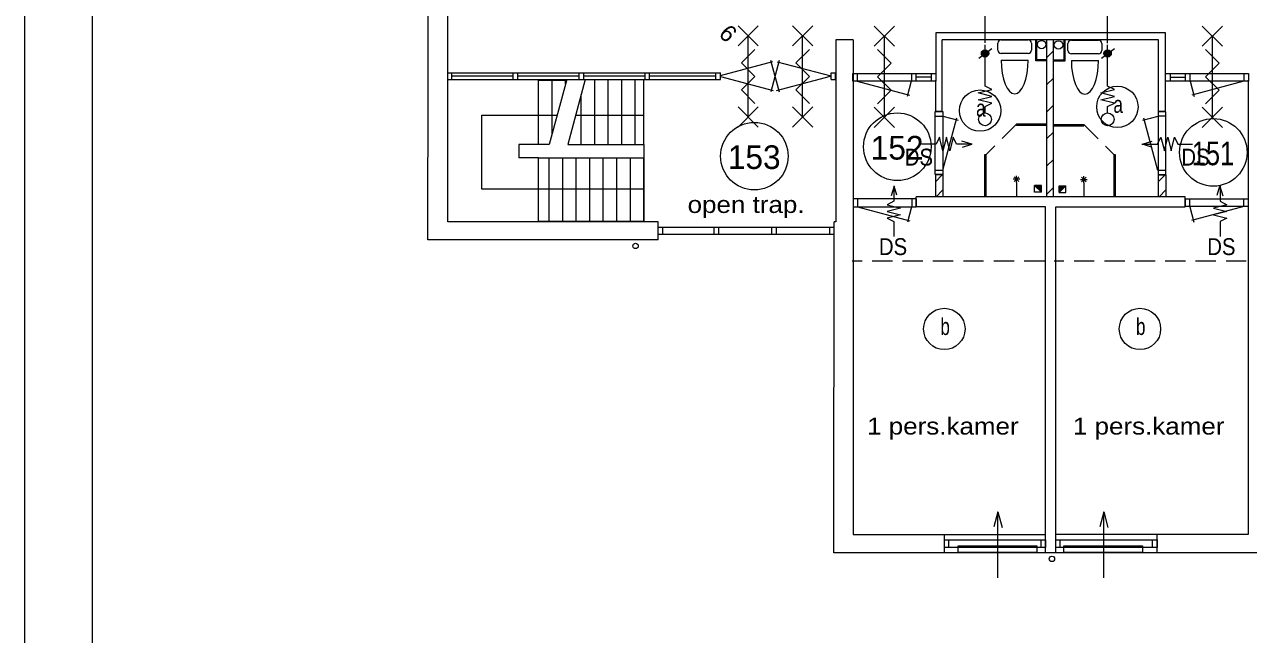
# Model space of a CAD drawing. Extents: x 295824 to 414724, y 24924 to 109024.
# Drawn here: x 295824 to 313944, y 61087 to 70117 of the extents above; entities that cross this region are included whole.
import ezdxf
from ezdxf.enums import TextEntityAlignment as Align

# ---------------------------------------------------------------- set-up
doc = ezdxf.new("R2010")
doc.units = 0
doc.header["$LTSCALE"] = 100
doc.linetypes.add('MEDIUM_DASHED', pattern=[4.5, 3, -1.5])
for name, color, linetype, lineweight in [('1', 7, 'Continuous', 13), ('16', 7, 'Continuous', 13), ('24', 7, 'Continuous', 13), ('61', 7, 'Continuous', 13)]:
    doc.layers.add(name, color=color, linetype=linetype, lineweight=lineweight)

msp = doc.modelspace()

# ---------------------------------------------------------------- hatches: boundary and pattern name
at = {"layer": '24'}
for points in [[(310097.8, 69688.9, 1), (309989.2, 69688.9, 1)], [(311913.3, 69688.9, 1), (311804.7, 69688.9, 1)]]:
    msp.add_hatch(color=256, dxfattribs=at).paths.add_polyline_path(points)
at = {"layer": '61'}
for points in [[(310777.4, 67734.4), (310877.4, 67634.4), (310877.4, 67734.4)], [(311239.8, 67729), (311139.8, 67629), (311139.8, 67729)]]:
    msp.add_hatch(color=256, dxfattribs=at).paths.add_polyline_path(points)

# ---------------------------------------------------------------- linework, layer by layer
at = {"layer": '1'}
for p, q in [((295823.6, 109023.8), (295823.6, 24923.8)), ((310043.5, 69843.4), (310043.5, 70726.3)), ((311859, 69838.4), (311859, 70726.3))]:
    msp.add_line(p, q, dxfattribs=at)
msp.add_lwpolyline([(304995.6, 108023.8), (296823.6, 108023.8), (296823.6, 25923.8), (304995.6, 25923.8)], dxfattribs=at)
at = {"layer": '16'}
for p, q in [((309470.8, 68447.5), (309420.8, 68247.5)), ((312748.2, 68447.5), (312798.2, 68247.5)), ((308594.4, 67349.3), (308794.4, 67299.3)), ((313624.7, 67349.3), (313424.7, 67299.3))]:
    msp.add_line(p, q, dxfattribs=at)
at = {"layer": '24'}
for p, q in [((310043.5, 69253.4), (310043.5, 69814.2)), ((311859, 69253.4), (311859, 69815.7)), ((309951.9, 69618), (310143.5, 69759.7)), ((311767.4, 69618), (311959, 69759.7)), ((309846.2, 68344.1), (309702, 68389.2)), ((309710.4, 68301.7), (309846.2, 68344.1)), ((312372.8, 68344.1), (312517, 68389.2)), ((312508.6, 68301.7), (312372.8, 68344.1)), ((308697.7, 67724.8), (308652.7, 67580.6)), ((308740.2, 67588.9), (308697.7, 67724.8)), ((313478.9, 67588.9), (313521.3, 67724.8)), ((313521.3, 67724.8), (313566.3, 67580.6)), ((310235, 62903.3), (310175.4, 62680.9)), ((311800.7, 62903.3), (311741.1, 62680.9))]:
    msp.add_line(p, q, dxfattribs=at)
for points in [[(310043.5, 68803.4), (310043.5, 68903.4), (310143.5, 68953.4), (309943.5, 69003.4), (310143.5, 69053.4), (309943.5, 69103.4), (310143.5, 69153.4), (310043.5, 69203.4), (310043.5, 69253.4)], [(311859, 68803.4), (311859, 68903.4), (311959, 68953.4), (311759, 69003.4), (311959, 69053.4), (311759, 69103.4), (311959, 69153.4), (311859, 69203.4), (311859, 69253.4)], [(309420.8, 68247.5), (309370.8, 68447.5), (309320.8, 68347.5), (309102, 68347.5)], [(309852, 68347.5), (309620.8, 68347.5), (309570.8, 68447.5), (309520.8, 68247.5), (309470.8, 68447.5)], [(312367, 68347.5), (312598.2, 68347.5), (312648.2, 68447.5), (312698.2, 68247.5), (312748.2, 68447.5)], [(312798.2, 68247.5), (312848.2, 68447.5), (312898.2, 68347.5), (313117, 68347.5)], [(308694.4, 67730.6), (308694.4, 67499.3), (308594.4, 67449.3), (308794.4, 67399.3), (308594.4, 67349.3)], [(313524.7, 67730.6), (313524.7, 67499.3), (313624.7, 67449.3), (313424.7, 67399.3), (313624.7, 67349.3)], [(308794.4, 67299.3), (308594.4, 67249.3), (308694.4, 67199.3), (308694.4, 66980.6)], [(313424.7, 67299.3), (313624.7, 67249.3), (313524.7, 67199.3), (313524.7, 66980.6)], [(310235, 61928.3), (310235, 62903.3), (310296.7, 62673.1)], [(311800.7, 61928.3), (311800.7, 62903.3), (311862.4, 62673.1)]]:
    msp.add_lwpolyline(points, dxfattribs=at)
for points in [[(309643.7, 62399.1), (310809.7, 62399.1), (310809.7, 62299.1), (309643.7, 62299.1)], [(311209.4, 62399.1), (312375.4, 62399.1), (312375.4, 62299.1), (311209.4, 62299.1)]]:
    msp.add_lwpolyline(points, close=True, dxfattribs=at)
for centre, radius in [((310043.5, 69688.9), 54.3), ((311859, 69688.9), 54.3), ((310043.5, 68711.8), 95), ((311859, 68711.8), 95)]:
    msp.add_circle(centre, radius, dxfattribs=at)
at = {"layer": '61'}
for p, q in [((302090.1, 69301.2), (302090.1, 72065.2)), ((306687.3, 70099), (306387.3, 69799)), ((306387.3, 70099), (306687.3, 69799)), ((306537.3, 68749), (306537.3, 69949)), ((307493.3, 70099), (307193.3, 69799)), ((307193.3, 70099), (307493.3, 69799)), ((307343.3, 68749), (307343.3, 69949)), ((308402.5, 69794.2), (308702.5, 70094.2)), ((308702.5, 69794.2), (308402.5, 70094.2)), ((313258.3, 69794.2), (313558.3, 70094.2)), ((313558.3, 69794.2), (313258.3, 70094.2)), ((308090.1, 69891.5), (308090.1, 62566.5)), ((308552.5, 69944.2), (308552.5, 68744.2)), ((309409.2, 68829.5), (309409.2, 69891.5)), ((310232.4, 69738.5), (310232.4, 69838.5)), ((310282.4, 69888.5), (310682.4, 69888.5)), ((310732.4, 69838.5), (310732.4, 69738.5)), ((310809.2, 69591.5), (310809.2, 69891.5)), ((310959.2, 67566.5), (310959.2, 69891.5)), ((311055.5, 67566.5), (311055.5, 69891.5)), ((311209.3, 69891), (311209.3, 69591)), ((311271.8, 69733.6), (311271.8, 69833.6)), ((311321.8, 69883.6), (311721.8, 69883.6)), ((311771.8, 69833.6), (311771.8, 69733.6)), ((313408.3, 69944.2), (313408.3, 68744.2)), ((306998.8, 69115.4), (306872.9, 69585.2)), ((310682.4, 69688.5), (310282.4, 69688.5)), ((310282.4, 69588.5), (310682.4, 69588.5)), ((310959.2, 69591.5), (310809.2, 69591.5)), ((311054.9, 69725.6), (310959.2, 69629.8)), ((311209.3, 69591), (311059.3, 69591)), ((311721.8, 69683.6), (311321.8, 69683.6)), ((311321.8, 69583.6), (311721.8, 69583.6)), ((306127.9, 69360.1), (306903.9, 69568.1)), ((306994, 69581.7), (306870.9, 69122.2)), ((306968.5, 69566.3), (307758.5, 69354.6)), ((302090.1, 67197.7), (302090.1, 69297.7)), ((302090.5, 69401.2), (306126.4, 69401.2)), ((302090.5, 69301.2), (306126.4, 69301.2)), ((302152.3, 69301), (302152.3, 69401)), ((302153.3, 69354.4), (303061.3, 69354.4)), ((303060.3, 69301), (303060.3, 69401)), ((303127.3, 69301), (303127.3, 69401)), ((303127.6, 69354.4), (304035.6, 69354.4)), ((303433.4, 68342.8), (303433.4, 69295.1)), ((303850.5, 69303.5), (303590.7, 68342.8)), ((303633.4, 68500.9), (303633.4, 69295.1)), ((303833.4, 69240.4), (303833.4, 69295.1)), ((304125.6, 69303.5), (303865.7, 68342.8)), ((304035.3, 69301), (304035.3, 69401)), ((304101.8, 69354.4), (305009.8, 69354.4)), ((304102.3, 69301), (304102.3, 69401)), ((304265.7, 68342.8), (304265.7, 69295.8)), ((304465.7, 68342.8), (304465.7, 69295.8)), ((304665.7, 68342.8), (304665.7, 69295.8)), ((304865.7, 68342.8), (304865.7, 69295.8)), ((305010.3, 69301), (305010.3, 69401)), ((305077.3, 69301), (305077.3, 69401)), ((305078.6, 69354.4), (306052.9, 69354.4)), ((306055.9, 69301), (306055.9, 69401)), ((306126.4, 69301.2), (306126.4, 69401.2)), ((306127.9, 69349.4), (306906.8, 69140.7)), ((306955.3, 69139.4), (307756.8, 69354.2)), ((307764.7, 69301.2), (307764.7, 69401.2)), ((307764.7, 69401.2), (307831.7, 69401.2)), ((307764.7, 69301.2), (307831.7, 69301.2)), ((307831.7, 69301.2), (307831.7, 69401.2)), ((307832.8, 69398.8), (307832.8, 67197.7)), ((308152.2, 69276.8), (308925, 69069.7)), ((308153, 69391.4), (308153, 69277.4)), ((308950.6, 69276.2), (308889.9, 69049.3)), ((308953, 69391.4), (308953, 69277.4)), ((309020, 69391.4), (309020, 69277.4)), ((309246, 69337.3), (309020, 69337.3)), ((309246, 69391.4), (309246, 69277.4)), ((309314.4, 68829.5), (309314.4, 69291.5)), ((311054.9, 69324.7), (310959.2, 69228.9)), ((312714.4, 68828), (312714.4, 69393.9)), ((312782.6, 69391.4), (312782.6, 69277.4)), ((312782.6, 69337.4), (313008.6, 69337.4)), ((313008.6, 69391.4), (313008.6, 69277.4)), ((313075.6, 69391.4), (313075.6, 69277.4)), ((313078, 69276.2), (313138.7, 69049.3)), ((313876.4, 69276.8), (313103.6, 69069.8)), ((313875.6, 69391.4), (313875.6, 69277.4)), ((313940.1, 69291.5), (313940.1, 62566.5)), ((304065.7, 68342.8), (304065.7, 69082.3)), ((306687.3, 68899), (306387.3, 68599)), ((306387.3, 68899), (306687.3, 68599)), ((307493.3, 68899), (307193.3, 68599)), ((307193.3, 68899), (307493.3, 68599)), ((308402.5, 68594.2), (308702.5, 68894.2)), ((308702.5, 68594.2), (308402.5, 68894.2)), ((311054.9, 68921.3), (310959.2, 68825.5)), ((313258.3, 68594.2), (313558.3, 68894.2)), ((313558.3, 68594.2), (313258.3, 68894.2)), ((303983.1, 68776.6), (304996.9, 68776.6)), ((309306.9, 67894.7), (309306.9, 68828.7)), ((309306.9, 68761.7), (309420.9, 68761.7)), ((309409.2, 68829.5), (309314.4, 68829.5)), ((309419, 67960.9), (309626, 68733.6)), ((309419.6, 68759.3), (309646.5, 68698.5)), ((312602.6, 68755.1), (312375.7, 68694.3)), ((312603.2, 67956.6), (312396.1, 68729.4)), ((312720.4, 68757.4), (312606.4, 68757.4)), ((312714.4, 68828), (312609.2, 68828)), ((312720.4, 67892), (312720.4, 68824.4)), ((310960.3, 68640.1), (310510.8, 68640.1)), ((310510.8, 68640.1), (310510.8, 68622.1)), ((310960, 68622.1), (310510.8, 68622.1)), ((311054.9, 68525.3), (310959.2, 68429.5)), ((311057, 68634.8), (311506.4, 68634.8)), ((311057.3, 68616.8), (311506.4, 68616.8)), ((311506.4, 68634.8), (311506.4, 68616.8)), ((303433.4, 68342.8), (303140.1, 68342.8)), ((303140.1, 68342.8), (303140.1, 68140.8)), ((304990.8, 68342.8), (304992.8, 68140.8)), ((303433.4, 68140.8), (303140.1, 68140.8)), ((303592.8, 67202.9), (303592.8, 68140.8)), ((303792.8, 67202.9), (303792.8, 68140.8)), ((303992.8, 67202.9), (303992.8, 68140.8)), ((304192.8, 67202.9), (304192.8, 68140.8)), ((304392.8, 67202.9), (304392.8, 68140.8)), ((304592.8, 67202.9), (304592.8, 68140.8)), ((304792.8, 67202.9), (304792.8, 68140.8)), ((304992.8, 67202.9), (304992.8, 68140.8)), ((310059.9, 67572.1), (310059.9, 68192.6)), ((311957.3, 67566.7), (311957.3, 68187.2)), ((309306.9, 67961.7), (309420.9, 67961.7)), ((311054.9, 68120.7), (310959.2, 68024.9)), ((312720.4, 67957.4), (312606.4, 67957.4)), ((309420.3, 67894.7), (309306.3, 67894.7)), ((309419.6, 67891.1), (309309.6, 67891.1)), ((309309.6, 67891.1), (309309.6, 67567.1)), ((309409.3, 67889.9), (309309.6, 67790.2)), ((309419.6, 67891.1), (309419.6, 67567.1)), ((310559.8, 67828.6), (310459.8, 67828.6)), ((310545.1, 67793.2), (310474.4, 67863.9)), ((310545.1, 67863.9), (310474.4, 67793.2)), ((310509.8, 67778.6), (310509.8, 67878.6)), ((310509.8, 67778.6), (310509.8, 67578.6)), ((311457.5, 67823.2), (311557.5, 67823.2)), ((311472.1, 67787.9), (311542.9, 67858.6)), ((311472.1, 67858.6), (311542.9, 67787.9)), ((311507.5, 67773.2), (311507.5, 67873.2)), ((311507.5, 67773.2), (311507.5, 67573.2)), ((312707.8, 67889.9), (312608.1, 67790.2)), ((312718.6, 67891.1), (312608.6, 67891.1)), ((312608.6, 67891.1), (312608.6, 67567.1)), ((312718.6, 67891.1), (312718.6, 67567.1)), ((309417.9, 67667.3), (309318.2, 67567.6)), ((311054.9, 67702.6), (310959.2, 67606.8)), ((312720.1, 67667.3), (312620.4, 67567.6)), ((308156.8, 67419.4), (308929.5, 67212.3)), ((308157.5, 67534), (308157.5, 67420)), ((308955.2, 67418.7), (308894.4, 67191.9)), ((308957.5, 67534), (308957.5, 67420)), ((309024.5, 67534), (309024.5, 67420)), ((309419.6, 67567.1), (309309.6, 67567.1)), ((310940.1, 62296.9), (310940.1, 67416.5)), ((311090.1, 62296.9), (311090.1, 67416.5)), ((312718.6, 67567.1), (312608.6, 67567.1)), ((313005.2, 67535.1), (313005.2, 67421.1)), ((313072.2, 67535.1), (313072.2, 67421.1)), ((313074.6, 67419.8), (313135.4, 67193)), ((313873, 67420.4), (313100.2, 67213.4)), ((313872.2, 67535.1), (313872.2, 67421.1)), ((305206.2, 67197.7), (302090.1, 67197.7)), ((305206.2, 66927.7), (305206.2, 67197.7)), ((305206.6, 67015.6), (305206.6, 67116.5)), ((305206.6, 67116.5), (307811.6, 67116.5)), ((305273.6, 67016.6), (305273.6, 67116.6)), ((306035.3, 67016.6), (306035.3, 67116.6)), ((306102.3, 67016.6), (306102.3, 67116.6)), ((306889.3, 67016.6), (306889.3, 67116.6)), ((306956.6, 67015.6), (306956.6, 67116.6)), ((307740.6, 67116.6), (307807.6, 67116.6)), ((307743.6, 67015.6), (307743.6, 67116.6)), ((307806, 62296.5), (307811.7, 67197.7)), ((307810.6, 67015.6), (307810.6, 67116.6)), ((307832.8, 67197.7), (307811.7, 67197.7)), ((305206.2, 66927.7), (301796.6, 66927.7)), ((305206.6, 67015.6), (307810.6, 67015.6)), ((308090.1, 62566.5), (310940.1, 62566.5)), ((309441.4, 62295.3), (309441.4, 62565.3)), ((313940.1, 62566.5), (311090.1, 62566.5)), ((312589.8, 62295.3), (312589.8, 62564.6)), ((309508.3, 62373.6), (309508.3, 62487.5)), ((310873.3, 62373), (310873.3, 62487)), ((311156.8, 62373.9), (311156.8, 62487.9)), ((312521.1, 62373.6), (312521.1, 62487.3)), ((326233, 62296.5), (307806, 62296.5))]:
    msp.add_line(p, q, dxfattribs=at)
at = {"layer": '61', "linetype": 'MEDIUM_DASHED'}
for p, q in [((310508.8, 68639.6), (310061.9, 68192.8)), ((311508.5, 68634.3), (311955.4, 68187.4)), ((310922.5, 66613.1), (308075.5, 66613.1)), ((313911.6, 66613.1), (311064.6, 66613.1))]:
    msp.add_line(p, q, dxfattribs=at)
at = {"layer": '61'}
for points in [[(301796.6, 66927.7), (301820.1, 79160.8), (332210.1, 79160.8)], [(312714.4, 69391.5), (312714.4, 69991.5), (309314.4, 69991.5), (309314.4, 69391.5)], [(308090.1, 69891.5), (307832.8, 69891.5), (307832.8, 69397.7)], [(312609.2, 68828), (312609.2, 69891.5), (309409.2, 69891.5)], [(310959.2, 69576.5), (310794.2, 69576.5), (310794.2, 69891.5)], [(311224.3, 69891), (311224.3, 69576), (311059.3, 69576)], [(306637.3, 68949), (306437.3, 69149), (306637.3, 69349), (306437.3, 69549), (306637.3, 69749)], [(307443.3, 68949), (307243.3, 69149), (307443.3, 69349), (307243.3, 69549), (307443.3, 69749)], [(308452.5, 69744.2), (308652.5, 69544.2), (308452.5, 69344.2), (308652.5, 69144.2), (308452.5, 68944.2)], [(313308.3, 69744.2), (313508.3, 69544.2), (313308.3, 69344.2), (313508.3, 69144.2), (313308.3, 68944.2)], [(303590.7, 68342.8), (303433.4, 68342.8), (303433.4, 69295.1), (303848.2, 69295.1)], [(303865.7, 68342.8), (304990.8, 68342.8), (304990.8, 69295.8), (304123.5, 69295.8)], [(304992.8, 67679.1), (302596, 67679.1), (302596, 68775.7), (303707.7, 68775.7)], [(310041.9, 67572.1), (310041.9, 68192.6), (310059.9, 68192.6)], [(311975.3, 67566.7), (311975.3, 68187.2), (311957.3, 68187.2)], [(310877.4, 67634.4), (310877.4, 67734.4), (310777.4, 67734.4)], [(311139.8, 67629), (311139.8, 67729), (311239.8, 67729)], [(308090.5, 67534), (308090.5, 67420), (309024.5, 67420)], [(309024.5, 67534), (308090.5, 67534), (308090.5, 67420)], [(311089.4, 67416.5), (313004.4, 67416.5), (313004.4, 67566.5), (309025, 67566.5)], [(310939.4, 67416.5), (309025, 67416.5), (309025, 67566.5)], [(313939.2, 67535.1), (313939.2, 67421.1), (313005.2, 67421.1)], [(313005.2, 67535.1), (313939.2, 67535.1), (313939.2, 67421.1)]]:
    msp.add_lwpolyline(points, dxfattribs=at)
for points in [[(309313, 69391.4), (309313, 69277.4), (308086, 69277.4), (308086, 69391.4)], [(309313, 69391.4), (309313, 69277.4), (308086, 69277.4), (308086, 69391.4)], [(313942.6, 69391.4), (313942.6, 69277.4), (312716.2, 69277.4), (312716.2, 69391.4)], [(313942.6, 69391.4), (313942.6, 69277.4), (312716.2, 69277.4), (312716.2, 69391.4)], [(309306.9, 67894.7), (309306.9, 68828.7), (309420.9, 68828.7), (309420.9, 67894.7)], [(312720.4, 68825.4), (312606.4, 68825.4), (312606.4, 67891.4), (312720.4, 67891.4)], [(304992.8, 67202.9), (303433.4, 67202.9), (303433.4, 68140.8), (304992.8, 68140.8)], [(310877.4, 67634.4), (310777.4, 67634.4), (310777.4, 67734.4)], [(310777.4, 67734.4), (310877.4, 67634.4), (310877.4, 67734.4)], [(311139.8, 67629), (311239.8, 67629), (311239.8, 67729)], [(311239.8, 67729), (311139.8, 67629), (311139.8, 67729)], [(309441.5, 62373.5), (309441.5, 62487.5), (310940.1, 62487.5), (310940.1, 62373.5)], [(311090.5, 62373.6), (311090.5, 62487.6), (312589.8, 62487.6), (312589.8, 62373.6)]]:
    msp.add_lwpolyline(points, close=True, dxfattribs=at)
for centre, radius in [((310881.7, 69819.1), 62.5), ((311131.7, 69813.5), 62.5), ((309970.3, 68842), 306.3), ((312002.7, 68897.8), 306.3), ((308745.1, 68307.1), 500), ((313422.4, 68223.6), 500), ((306629.1, 68167.8), 500), ((304869.4, 66838.8), 40), ((309441.3, 65610.1), 306.3), ((312336.8, 65610.1), 306.3), ((311034.3, 62206.5), 40)]:
    msp.add_circle(centre, radius, dxfattribs=at)
for centre, start, end in [((310282.4, 69838.5), 90, 180), ((310682.4, 69838.5), 0, 90), ((311321.8, 69833.6), 90, 180), ((311721.8, 69833.6), 0, 90), ((310282.4, 69738.5), 180, 270), ((310682.4, 69738.5), 270, 0), ((311321.8, 69733.6), 180, 270), ((311721.8, 69733.6), 270, 0)]:
    msp.add_arc(centre, 50, start, end, dxfattribs=at)
for centre in [(310482.4, 69588.5), (311521.8, 69583.6)]:
    msp.add_ellipse(centre, major_axis=(0, -500), ratio=0.4, start_param=4.712389, end_param=7.8539816, dxfattribs=at)

# ---------------------------------------------------------------- texts
at = {"layer": '24', "width": 0.9}
for p in [(308855.6, 68028.5), (312950, 68028.5), (308472.5, 66703.6), (313333.1, 66703.6)]:
    msp.add_text('DS', height=250, dxfattribs=at).set_placement(p)
at = {"layer": '61'}
msp.add_text('6', height=250, rotation=315, dxfattribs=at).set_placement((306086.5, 69963.1))
for s, width, p in [('a', 0.75, (309912.3, 68752.8)), ('a', 0.75, (311944.7, 68808.6)), ('open trap.', 1.15, (305640.4, 67327)), ('b', 0.75, (309383.3, 65520.9)), ('b', 0.75, (312278.8, 65520.9)), ('1 pers.kamer', 1.15, (308297.5, 64046.9)), ('1 pers.kamer', 1.15, (311344.4, 64046.9))]:
    msp.add_text(s, height=250, dxfattribs=dict(at, width=width)).set_placement(p)
for s, p in [('153', (306626.2, 67978)), ('152', (308742.1, 68117.3))]:
    msp.add_text(s, height=350, dxfattribs=at).set_placement(p, align=Align.CENTER)
at = {"layer": '61', "width": 0.8}
msp.add_text('151', height=350, dxfattribs=at).set_placement((313418.1, 68033.7), align=Align.CENTER)

doc.saveas('drawing.dxf')
